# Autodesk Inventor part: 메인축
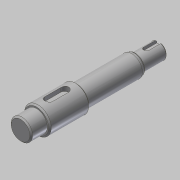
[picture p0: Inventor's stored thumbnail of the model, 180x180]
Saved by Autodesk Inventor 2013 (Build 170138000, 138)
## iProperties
Created: 2019-03
Part Number: 메인축
Material: 강철, 연강
Document SubType Name: Modeling
Designer: mduedu
Density: 1 g/cm^3
Author: mduedu
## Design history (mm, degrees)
sketch "스케치1"
  geometry: L1 (0, 0)-(12, 0); L2 (12, 0)-(12, 8); L3 (12, 8)-(0, 8); L4 (0, 8)-(0, 0); L5 (12, 0)-(42, 0); L6 (42, 0)-(42, 10); L7 (42, 10)-(12, 10); L8 (12, 10)-(12, 0); L9 (42, 0)-(86, 0); L10 (86, 0)-(86, 8); L11 (86, 8)-(42, 8); L12 (42, 8)-(42, 0); L13 (86, 0)-(104, 0); L14 (104, 0)-(104, 6); L15 (104, 6)-(86, 6); L16 (86, 6)-(86, 0)
  constraints: 32 end point, 8 parallel, 4 horizontal, 4 perpendicular
  dimensions: "d0" = 16 diameter of L3 L1; "d2" = 20 diameter of L7 L5; "d3" = 16 diameter of L11 L9; "d4" = 12 diameter of L15 L13; "d5" = 12 distance of L2.end L3.end; "d6" = 30 distance of L6.end L7.end; "d7" = 86 distance between parallel lines of L10 L4; "d8" = 104 distance between parallel lines of L14 L4
revolve "회전1" sketch "스케치1" stored, may be unused: angle "d9" = 90 deg
node "작업 평면1"
sketch "스케치2" dims "d10" = 18
  geometry: L1 (6, -3)-(-6, -3); L2 (-6, -3)-(-6, 3); L3 (-6, 3)-(6, 3); L4 (6, 3)-(6, -3); L5 (15, 10)-(15, -10) reference; 3 further points
  constraints: 8 end point, 2 midpoint, 2 parallel, 2 vertical alignment, 1 horizontal, 1 horizontal alignment, 1 perpendicular, 4 other
  dimensions: "d12" = 6 distance between parallel lines of L3 L1; "d13" = 6 dimension on L5
extrude "돌출1" cut sketch "스케치2" distance "d14" = 3.5; taper "d15" = 0 deg
node "작업 평면2"
sketch "스케치3"
  geometry: L1 (-9, 6)-(-9, -6) reference; L2 (1, -2)-(-9, -2); L3 (1, 2)-(-9, 2); A1 r 2 centre (1, 0) between (1, -2) and (1, 2); 2 further points
  constraints: 4 end point, 2 point on circle, 2 point on line, 2 tangent, 1 centre point, 1 horizontal alignment, 1 midpoint, 1 parallel, 1 perpendicular
  dimensions: "d16" = 12 dimension on A1 L1; "d17" = 4 distance between parallel lines of L3 L2
extrude "돌출2" cut sketch "스케치3" distance "d18" = 2.5; taper "d19" = 0 deg
chamfer "모따기1" distance "d20" = 1; stored, may be unused: second distance "d21" = 2, angle "d22" = 45 deg
chamfer "모따기2" distance "d23" = 1; stored, may be unused: second distance "d24" = 2, angle "d25" = 45 deg
chamfer "모따기3" distance "d26" = 1.73; stored, may be unused: second distance "d27" = 2, angle "d28" = 30 deg
fillet "모깎기2" dims "d31" = 0.5, "d32" = 4
node "솔리드1"
